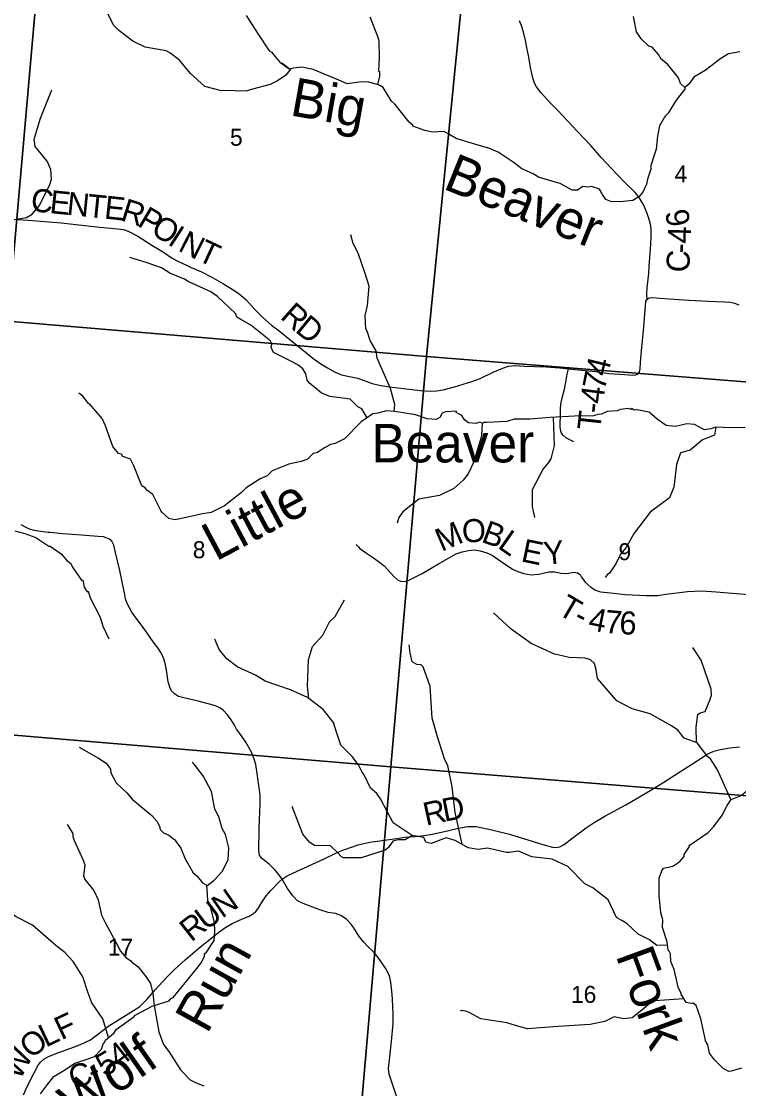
# Model space of a CAD drawing. Extents: x 1878108 to 2183446, y 146837 to 508383.
# Drawn here: x 1986826 to 1996150, y 297184 to 311060 of the extents above; entities that cross this region are included whole.
import ezdxf

# ---------------------------------------------------------------- set-up
doc = ezdxf.new("R2010")
doc.units = 0
for name, color, linetype in [('GM_X_County_Road', 7, 'Continuous'), ('GM_X_County_Road_Text', 7, 'Continuous'), ('GM_X_Minor_River', 7, 'Continuous'), ('GM_X_Minor_River_Text', 7, 'Continuous'), ('GM_X_Section', 7, 'Continuous'), ('GM_X_Section_Text', 7, 'Continuous'), ('GM_X_Township_Road', 7, 'Continuous'), ('GM_X_Township_Road_Text', 7, 'Continuous'), ('GM_X_Township_ROW', 7, 'Continuous')]:
    doc.layers.add(name, color=color, linetype=linetype)

msp = doc.modelspace()

# ---------------------------------------------------------------- linework, layer by layer
at = {"layer": 'GM_X_County_Road'}
for points in [[(1994960, 307449), (1994957, 307507), (1994963, 307594), (1994981, 307783), (1994989, 307875), (1995001, 308047), (1995007, 308171), (1995011, 308248), (1995014, 308347), (1995008, 308402), (1994987, 308485), (1994960, 308560), (1994920, 308657), (1994896, 308706), (1994855, 308771), (1994803, 308835), (1994676, 308961), (1994568, 309071), (1994364, 309291), (1994230, 309445), (1994052, 309634), (1993799, 309900), (1993706, 309996), (1993580, 310133), (1993523, 310210), (1993498, 310257), (1993478, 310310), (1993464, 310365), (1993446, 310458), (1993421, 310593), (1993406, 310677), (1993380, 310809), (1993358, 310903), (1993331, 310991), (1993301, 311066)], [(1986713, 308487), (1986919, 308474), (1987126, 308459), (1987343, 308440), (1987650, 308407), (1987845, 308386), (1988075, 308362), (1988153, 308354), (1988216, 308333), (1988338, 308266), (1988524, 308150), (1988674, 308058), (1988787, 307982), (1988860, 307942), (1988971, 307888), (1989033, 307861), (1989169, 307802), (1989301, 307733), (1989453, 307648), (1989613, 307548), (1989679, 307500), (1989742, 307444), (1989791, 307391), (1989856, 307317), (1989966, 307209), (1990078, 307110), (1990176, 307035), (1990268, 306963), (1990471, 306797), (1990616, 306682), (1990720, 306606), (1990806, 306554), (1990907, 306497), (1990989, 306466), (1991091, 306444), (1991196, 306422), (1991282, 306389), (1991387, 306351), (1991500, 306325), (1991647, 306304), (1991793, 306285), (1992010, 306260), (1992143, 306251), (1992224, 306257), (1992307, 306270), (1992458, 306308), (1992571, 306343), (1992683, 306376), (1992792, 306418), (1992958, 306497), (1993085, 306551), (1993159, 306576), (1993240, 306584), (1993362, 306577), (1993501, 306572), (1993648, 306568), (1993827, 306556), (1993937, 306544), (1994153, 306519), (1994291, 306509), (1994461, 306482), (1994669, 306467), (1994766, 306462), (1994813, 306465), (1994840, 306475), (1994861, 306502), (1994872, 306542), (1994875, 306625), (1994891, 306825), (1994912, 307037), (1994938, 307358), (1994943, 307421), (1994960, 307449)], [(1994960, 307449), (1994986, 307464), (1995029, 307470), (1995125, 307463), (1995504, 307435), (1995758, 307422), (1995971, 307415), (1996044, 307407), (1996098, 307396), (1996154, 307374)], [(1987175, 304416), (1987078, 304427), (1986998, 304442), (1986931, 304459), (1986880, 304482), (1986824, 304512)], [(1991702, 297087), (1991632, 297293), (1991605, 297372), (1991599, 297444), (1991611, 297557), (1991637, 297797), (1991660, 298031), (1991659, 298130), (1991653, 298261), (1991645, 298414), (1991628, 298569), (1991616, 298633), (1991598, 298682), (1991559, 298752), (1991495, 298845), (1991452, 298906), (1991406, 298958), (1991326, 299037), (1991281, 299086), (1991217, 299164), (1991149, 299274), (1991110, 299329), (1991051, 299388), (1990979, 299436), (1990910, 299461), (1990813, 299474), (1990707, 299508), (1990487, 299590), (1990416, 299627), (1990354, 299690), (1990285, 299786), (1990215, 299908), (1990167, 299972), (1990127, 300024), (1990096, 300056), (1990048, 300104), (1989992, 300145), (1989943, 300184), (1989922, 300219), (1989912, 300274), (1989911, 300374), (1989916, 300461), (1989918, 300575), (1989921, 300685), (1989927, 300779), (1989930, 300884), (1989928, 301005), (1989916, 301093), (1989897, 301249), (1989872, 301400), (1989853, 301468), (1989817, 301560), (1989744, 301689), (1989666, 301802), (1989624, 301858), (1989596, 301909), (1989555, 301980), (1989504, 302042), (1989452, 302100), (1989404, 302135), (1989349, 302162), (1989273, 302184), (1989125, 302222), (1988957, 302261), (1988869, 302283), (1988816, 302318), (1988779, 302356), (1988755, 302403), (1988734, 302475), (1988715, 302600), (1988699, 302696), (1988676, 302773), (1988646, 302841), (1988601, 302914), (1988538, 302994), (1988443, 303132), (1988375, 303227), (1988320, 303302), (1988264, 303379), (1988232, 303433), (1988202, 303492), (1988181, 303552), (1988166, 303628), (1988141, 303751), (1988106, 303920), (1988051, 304154), (1988030, 304250), (1988002, 304301), (1987972, 304329), (1987930, 304345), (1987892, 304357), (1987819, 304362), (1987606, 304379), (1987365, 304398), (1987196, 304414), (1987175, 304416)], [(1986852, 297102), (1986907, 297219), (1986989, 297383), (1987041, 297481), (1987071, 297525), (1987116, 297566), (1987178, 297601), (1987299, 297649), (1987470, 297710), (1987593, 297759), (1987724, 297817), (1987965, 298001), (1988146, 298112), (1988285, 298202), (1988365, 298253), (1988458, 298342), (1988571, 298471), (1988662, 298574), (1988730, 298648), (1988817, 298733), (1988956, 298860), (1989138, 299015), (1989323, 299162), (1989409, 299232), (1989485, 299284), (1989565, 299331), (1989632, 299362), (1989690, 299388), (1989786, 299428), (1989844, 299460), (1989875, 299489), (1989903, 299525), (1989947, 299601), (1990008, 299691), (1990068, 299760), (1990177, 299875), (1990215, 299908), (1990283, 299951), (1990409, 300012), (1990704, 300147), (1990968, 300270), (1991106, 300320), (1991205, 300353), (1991357, 300387), (1991514, 300409), (1991701, 300437), (1991813, 300455), (1991944, 300464), (1992064, 300474), (1992168, 300492), (1992365, 300537), (1992507, 300572), (1992628, 300592), (1992736, 300592), (1992942, 300547), (1993173, 300494), (1993605, 300357), (1993731, 300323), (1993775, 300319), (1993826, 300326), (1993881, 300357), (1993980, 300436), (1994167, 300575), (1994272, 300644), (1994410, 300725), (1994682, 300875), (1995009, 301063), (1995178, 301168), (1995374, 301293), (1995611, 301447), (1995733, 301529), (1995828, 301572), (1995913, 301594), (1996034, 301613), (1996162, 301627)]]:
    msp.add_lwpolyline(points, dxfattribs=at)
at = {"layer": 'GM_X_Minor_River'}
for points in [[(1988707, 310676), (1988437, 310726), (1988277, 310803), (1988094, 310941), (1988024, 311009), (1987945, 311171), (1987913, 311293)], [(1989747, 311136), (1989905, 310894), (1990046, 310677), (1990076, 310657), (1990187, 310531), (1990320, 310434), (1990211, 310515)], [(1991356, 311119), (1991457, 310865), (1991471, 310805), (1991476, 310589), (1991468, 310415), (1991480, 310407), (1991482, 310345), (1991456, 310238)], [(1995452, 310198), (1995395, 310252), (1995367, 310326), (1995281, 310432), (1995227, 310502), (1995142, 310570), (1995110, 310628), (1995026, 310722), (1994984, 310738), (1994883, 310832), (1994821, 310923), (1994785, 311123)], [(1996165, 310664), (1996017, 310636), (1995917, 310575), (1995713, 310419), (1995569, 310333), (1995504, 310243), (1995452, 310198), (1995450, 310176), (1995340, 310034), (1995234, 309864), (1995199, 309832), (1995187, 309814), (1995123, 309702), (1995095, 309568), (1995076, 309396), (1995042, 309294), (1995004, 309170), (1995014, 309150), (1994965, 309009), (1994953, 308941), (1994905, 308841), (1994853, 308777), (1994775, 308731), (1994611, 308713), (1994489, 308719), (1994423, 308744), (1994379, 308810), (1994371, 308824), (1994342, 308876), (1994236, 308912), (1994184, 308906), (1994126, 308912), (1994056, 308866), (1993986, 308864), (1993828, 308953), (1993764, 308969), (1993549, 309033), (1993477, 309077), (1993331, 309144), (1993219, 309230), (1993022, 309358), (1992890, 309416), (1992880, 309416), (1992605, 309497), (1992477, 309537), (1992383, 309595), (1992321, 309627), (1992171, 309620), (1992069, 309640), (1991916, 309698), (1991914, 309710), (1991868, 309748), (1991687, 309980), (1991637, 310024), (1991527, 310201), (1991485, 310225), (1991467, 310233), (1991324, 310273), (1991218, 310267), (1991062, 310247), (1990952, 310296), (1990619, 310434), (1990471, 310465), (1990361, 310453), (1990327, 310443), (1990265, 310361), (1990155, 310285), (1990059, 310237), (1989831, 310176), (1989745, 310154), (1989449, 310160), (1989429, 310157), (1989211, 310211), (1989024, 310381), (1988880, 310554), (1988757, 310652), (1988707, 310676)], [(1991486, 310335), (1991486, 310335)], [(1986736, 308484), (1986894, 308511), (1986967, 308552), (1987059, 308663), (1987180, 308900), (1987197, 308939), (1987217, 309008), (1987210, 309135), (1987163, 309241), (1987007, 309431), (1986992, 309528), (1987073, 309800), (1987220, 310168)], [(1991674, 305990), (1991680, 306077), (1991626, 306287), (1991452, 306679), (1991440, 306777), (1991358, 306909), (1991321, 307031), (1991303, 307064), (1991293, 307237), (1991326, 307365), (1991346, 307619), (1991289, 307793), (1991206, 308048), (1991140, 308172), (1991110, 308286)], [(1991321, 305906), (1991250, 306022), (1991198, 306050), (1991102, 306146), (1990837, 306184), (1990721, 306229), (1990573, 306357), (1990540, 306395), (1990522, 306477), (1990484, 306541), (1990420, 306595), (1990310, 306649), (1990105, 306756), (1990071, 306820), (1990083, 306866), (1990065, 306902), (1990047, 306918), (1989810, 307112), (1989680, 307182), (1989625, 307215), (1989611, 307263), (1989377, 307481), (1989288, 307545), (1988996, 307676), (1988946, 307710), (1988755, 307784), (1988647, 307854), (1988463, 307919), (1988235, 307988)], [(1990907, 305570), (1990843, 305559), (1990767, 305513), (1990677, 305453), (1990617, 305441), (1990547, 305369), (1990463, 305337), (1990441, 305333), (1990301, 305302), (1990087, 305218), (1990022, 305150), (1989930, 305112), (1989748, 304997), (1989688, 304933), (1989466, 304761), (1989294, 304674), (1989180, 304656), (1988892, 304590), (1988820, 304578), (1988742, 304595), (1988652, 304679), (1988640, 304701), (1988535, 304909), (1988455, 304965), (1988437, 304995), (1988391, 305023), (1988288, 305281), (1988246, 305367), (1988143, 305404), (1988129, 305432), (1988089, 305442), (1988015, 305534), (1987918, 305802), (1987878, 305898), (1987711, 306088), (1987699, 306092), (1987627, 306188), (1987571, 306227)], [(1996235, 305779), (1996040, 305775), (1995854, 305785), (1995790, 305762), (1995706, 305748), (1995576, 305820), (1995478, 305828), (1995328, 305794), (1995208, 305807), (1995093, 305889), (1994985, 305979), (1994827, 306007), (1994817, 306009), (1994793, 306005), (1994757, 306027), (1994749, 306015), (1994717, 306027), (1994615, 306012), (1994569, 305994), (1994439, 305986), (1994369, 305952), (1994319, 305950), (1994263, 305932), (1994016, 305927), (1993700, 305909), (1993436, 305888), (1993234, 305886), (1993148, 305860), (1993136, 305858), (1992876, 305843), (1992834, 305845), (1992830, 305833), (1992782, 305847), (1992736, 305831), (1992640, 305841), (1992587, 305881), (1992551, 305937), (1992477, 305976), (1992481, 305991), (1992339, 305984), (1992295, 305964), (1992271, 305920), (1992267, 305910), (1992219, 305884), (1992101, 305894), (1991949, 305942), (1991682, 305989), (1991572, 305997), (1991460, 305965), (1991394, 305955), (1991241, 305852), (1991025, 305630), (1990907, 305570)], [(1992817, 305837), (1992809, 305675), (1992798, 305639), (1992707, 305334), (1992636, 305176), (1992570, 305096), (1992448, 304988), (1992261, 304894), (1991993, 304846), (1991783, 304683), (1991731, 304608), (1991712, 304535)], [(1993741, 305911), (1993752, 305544), (1993708, 305370), (1993672, 305322), (1993611, 305240), (1993465, 304969), (1993465, 304751), (1993495, 304608)], [(1995853, 305784), (1995836, 305680), (1995679, 305618), (1995518, 305484), (1995395, 305448), (1995342, 305299), (1995306, 305004), (1995252, 304863), (1995000, 304679), (1994791, 304406), (1994685, 304216), (1994615, 304132), (1994559, 304015), (1994472, 303884), (1994442, 303862), (1994414, 303828)], [(1986741, 304438), (1986871, 304400), (1987016, 304348), (1987184, 304236), (1987200, 304235), (1987342, 304139), (1987415, 304051), (1987469, 304013), (1987489, 303963), (1987607, 303795), (1987624, 303793), (1987642, 303703), (1987682, 303643), (1987694, 303651), (1987720, 303567), (1987849, 303312), (1987887, 303198), (1987962, 303034)], [(1990564, 302258), (1990545, 302418), (1990558, 302757), (1990612, 302931), (1990745, 303080), (1990831, 303252), (1990904, 303323), (1991028, 303540)], [(1996050, 300942), (1995991, 301068), (1995876, 301327), (1995783, 301470), (1995749, 301499), (1995611, 301679), (1995440, 301739), (1995359, 301843), (1995277, 301903), (1994998, 302059), (1994765, 302121), (1994568, 302227), (1994314, 302517), (1994298, 302631), (1994275, 302713), (1994224, 302757), (1994155, 302780), (1993949, 302788), (1993801, 302826), (1993755, 302833), (1993453, 302970), (1993191, 303157), (1992962, 303368)], [(1995227, 299051), (1995087, 299044), (1994990, 299119), (1994846, 299191), (1994701, 299328), (1994631, 299369), (1994562, 299408), (1994453, 299640), (1994255, 299797), (1994152, 299848), (1993928, 300074), (1993724, 300167), (1993463, 300198), (1993289, 300273), (1993167, 300253), (1993133, 300255), (1992886, 300312), (1992762, 300292), (1992635, 300313), (1992463, 300409), (1992347, 300445), (1992153, 300372), (1992085, 300387), (1992056, 300449), (1991905, 300476), (1991661, 300639), (1991493, 300950), (1991446, 301020), (1991366, 301089), (1991284, 301262), (1991256, 301300), (1991210, 301392), (1991127, 301504), (1990979, 301649), (1990924, 301817), (1990882, 301945), (1990747, 302115), (1990545, 302270), (1990323, 302369), (1989997, 302482), (1989870, 302559), (1989630, 302670), (1989499, 302773), (1989399, 302895), (1989343, 303029)], [(1992554, 300363), (1992464, 300775), (1992426, 301106), (1992369, 301385), (1992330, 301460), (1992237, 301758), (1992166, 302002), (1992138, 302414), (1992048, 302666), (1992022, 302694), (1991966, 302700), (1991906, 302734), (1991878, 302848), (1991869, 302952)], [(1995603, 301682), (1995599, 301883), (1995618, 302049), (1995652, 302072), (1995715, 302086), (1995775, 302233), (1995798, 302300), (1995793, 302378), (1995662, 302755), (1995553, 302920)], [(1987578, 301623), (1987830, 301481), (1987928, 301414), (1987983, 301336), (1987987, 301290), (1988057, 301160), (1988196, 301032), (1988266, 300946), (1988400, 300834), (1988523, 300737), (1988589, 300663), (1988621, 300595), (1988631, 300553), (1988675, 300509), (1988744, 300479), (1988806, 300429), (1988818, 300425), (1988898, 300309), (1988957, 300173), (1989059, 299992), (1989105, 299950), (1989180, 299860), (1989240, 299824)], [(1987076, 297118), (1987167, 297238), (1987247, 297342), (1987399, 297435), (1987519, 297515), (1987693, 297573), (1987775, 297601), (1987869, 297699), (1987894, 297775), (1987906, 297785), (1987918, 297814), (1988034, 297910), (1988060, 297954), (1988294, 298122), (1988304, 298140), (1988526, 298255), (1988746, 298325), (1988767, 298357), (1988801, 298371), (1988957, 298561), (1989107, 298744), (1989164, 298820), (1989206, 298902), (1989206, 298938), (1989234, 298960), (1989242, 298972), (1989332, 299110), (1989343, 299226), (1989335, 299344), (1989289, 299530), (1989252, 299632), (1989242, 299784), (1989238, 299822), (1989334, 299896), (1989437, 300008), (1989513, 300157), (1989525, 300313), (1989480, 300488), (1989438, 300568), (1989426, 300596), (1989395, 300720), (1989343, 300818), (1989296, 301048), (1989194, 301242), (1989121, 301344), (1989049, 301428)], [(1996000, 300865), (1996051, 300943), (1996181, 300997), (1996402, 301179), (1996485, 301245), (1996685, 301266), (1996779, 301193), (1996820, 301126), (1996939, 301066), (1997081, 301036), (1997422, 300852), (1997484, 300843), (1997576, 300872)], [(1991909, 300475), (1991815, 300421), (1991726, 300421), (1991655, 300402), (1991599, 300319), (1991554, 300286), (1991435, 300244), (1991244, 300185), (1991015, 300184), (1990986, 300196), (1990934, 300256), (1990845, 300343), (1990636, 300345), (1990577, 300385), (1990506, 300466), (1990486, 300494), (1990348, 300851)], [(1996186, 297449), (1996054, 297412), (1996022, 297408), (1995951, 297446), (1995835, 297560), (1995773, 297646), (1995748, 297754), (1995720, 297804), (1995718, 297816), (1995659, 298092), (1995597, 298266), (1995559, 298297), (1995531, 298293), (1995467, 298305), (1995402, 298411), (1995404, 298423), (1995366, 298503), (1995338, 298621), (1995313, 298731), (1995267, 298839), (1995265, 298937), (1995245, 298971), (1995235, 298985), (1995222, 299093), (1995160, 299281), (1995166, 299379), (1995137, 299469), (1995115, 299695), (1995118, 299919), (1995152, 300017), (1995174, 300049), (1995296, 300077), (1995386, 300139), (1995441, 300203), (1995443, 300229), (1995513, 300333), (1995507, 300345), (1995519, 300355), (1995753, 300516), (1995825, 300586), (1995930, 300730), (1996000, 300865)], [(1987422, 300617), (1987497, 300501), (1987493, 300459), (1987517, 300401), (1987630, 300153), (1987650, 300095), (1987634, 299951), (1987650, 299905), (1987767, 299761), (1987825, 299639), (1987868, 299439), (1987914, 299346), (1988061, 299072), (1988115, 298970), (1988188, 298886), (1988246, 298848), (1988256, 298834), (1988342, 298770), (1988446, 298644), (1988503, 298553), (1988537, 298421), (1988552, 298263)], [(1987960, 297848), (1987883, 298091), (1987742, 298298), (1987688, 298440), (1987625, 298639), (1987500, 298839), (1987392, 298955), (1987273, 299047), (1986972, 299309), (1986758, 299418), (1986690, 299471), (1986511, 299675), (1986248, 299831), (1986148, 299945), (1986111, 300116), (1986098, 300308), (1986096, 300340)], [(1995438, 298352), (1995062, 298326), (1995025, 298316), (1994893, 298205), (1994766, 298103), (1994652, 298090), (1994532, 298117), (1994409, 298055), (1994221, 298017), (1993804, 297993), (1993406, 297962), (1993250, 298005), (1993136, 298041), (1992800, 298092), (1992647, 298173), (1992602, 298192), (1992543, 298200), (1992533, 298190)], [(1988553, 298264), (1988613, 297923), (1988673, 297757), (1988745, 297669), (1988896, 297429), (1989021, 297298), (1989097, 297258), (1989198, 297222)]]:
    msp.add_lwpolyline(points, dxfattribs=at)
at = {"layer": 'GM_X_Section'}
for points in [[(1987122, 312538), (1986650, 307162), (1981193, 307678), (1981689, 313028)], [(1987478, 312502), (1992620, 312034), (1992094, 306704), (1986650, 307162), (1987122, 312538)], [(1992928, 312010), (1998077, 311612), (1997595, 306264), (1992094, 306704), (1992620, 312034)], [(1992094, 306704), (1991629, 301367), (1986164, 301829), (1986650, 307162)], [(1997595, 306264), (1997113, 300923), (1991629, 301367), (1992094, 306704)], [(1986164, 301829), (1991629, 301367), (1991165, 296023), (1985670, 296467)], [(1997113, 300923), (1996673, 295553), (1991165, 296023), (1991629, 301367)]]:
    msp.add_lwpolyline(points, close=True, dxfattribs=at)
at = {"layer": 'GM_X_Township_Road'}
for points in [[(1994008, 305595), (1993965, 305613), (1993913, 305642), (1993872, 305674), (1993846, 305705), (1993837, 305731), (1993829, 305782), (1993831, 305832), (1993836, 305930), (1993835, 306018), (1993837, 306081), (1993855, 306167), (1993885, 306279), (1993905, 306368), (1993920, 306472), (1993937, 306544)], [(1991213, 304222), (1991223, 304210), (1991299, 304156), (1991402, 304086), (1991484, 304025), (1991543, 303979), (1991594, 303926), (1991668, 303842), (1991717, 303800), (1991758, 303782), (1991808, 303777), (1991854, 303791), (1992036, 303880), (1992247, 304007), (1992478, 304135), (1992554, 304161), (1992639, 304181), (1992711, 304190), (1992789, 304178), (1992876, 304152), (1992947, 304121), (1993050, 304045), (1993209, 303939), (1993280, 303907), (1993356, 303883), (1993451, 303866), (1993551, 303872), (1993681, 303901), (1993758, 303901), (1993845, 303887), (1993915, 303883), (1993986, 303896)], [(1993986, 303896), (1994005, 303900), (1994056, 303892), (1994091, 303867), (1994109, 303835), (1994154, 303768), (1994227, 303704), (1994291, 303664), (1994354, 303641), (1994526, 303626), (1994676, 303609), (1994948, 303597), (1995096, 303597), (1995202, 303611), (1995484, 303649), (1995672, 303657), (1995857, 303644), (1996329, 303603)]]:
    msp.add_lwpolyline(points, dxfattribs=at)
at = {"layer": 'GM_X_Township_ROW'}
msp.add_lwpolyline([(1991180, 304259), (1991213, 304222)], dxfattribs=at)

# ---------------------------------------------------------------- texts
at = {"layer": 'GM_X_County_Road_Text'}
for s, rotation, p in [('C', 354.2374, (1986940, 308593)), ('E', 354.2348, (1987185, 308568)), ('N', 354.2382, (1987408, 308546)), ('T', 354.2303, (1987671, 308519)), ('E', 353.8986, (1987894, 308497)), ('R', 342.4932, (1988102, 308476)), ('P', 329.1206, (1988320, 308410)), ('6', 100.6895, (1995527, 308422)), ('O', 328.6708, (1988493, 308306)), ('I', 326.875, (1988716, 308170)), ('N', 333.1151, (1988850, 308085)), ('4', 88.7124, (1995528, 308169)), ('T', 335.1134, (1989096, 307961)), ('C', 86.487, (1995505, 307788)), ('-', 86.7065, (1995521, 308035)), ('R', 318.1671, (1990178, 307206)), ('D', 320.7641, (1990372, 307032)), ('D', 11.0181, (1992325, 300653)), ('R', 12.4945, (1992086, 300600)), ('N', 34.7307, (1989435, 299391)), ('U', 36.7001, (1989226, 299234)), ('R', 38.302, (1989034, 299083)), ('F', 25.2198, (1987346, 297812)), ('O', 37.9464, (1986950, 297563)), ('L', 25.3968, (1987143, 297716)), ('4', 38.0542, (1988100, 297448)), ('W', 61.5774, (1986805, 297282)), ('5', 30.7039, (1987907, 297330)), ('C', 19.6143, (1987504, 297171)), ('-', 23.6887, (1987758, 297262))]:
    msp.add_text(s, height=300, rotation=rotation, dxfattribs=at).set_placement(p)
at = {"layer": 'GM_X_Minor_River_Text'}
for s, rotation, p in [('Big', 349.9997, (1990305, 309840)), ('Beaver', 337.9972, (1992292, 308889)), ('Beaver', 359.9996, (1991375, 305326)), ('Little', 28.0034, (1989354, 304034)), ('Run', 61.0006, (1989241, 297884)), ('Fork', 290.106, (1994548, 298918)), ('Wolf', 35.0008, (1987543, 296734))]:
    msp.add_text(s, height=500, rotation=rotation, dxfattribs=at).set_placement(p)
at = {"layer": 'GM_X_Section_Text'}
for s, p in [('5', (1989538, 309442)), ('4', (1995317, 308966)), ('8', (1989054, 304080)), ('9', (1994589, 304054)), ('17', (1987950, 298913)), ('16', (1993971, 298299))]:
    msp.add_text(s, height=221, rotation=0, dxfattribs=at).set_placement(p)
at = {"layer": 'GM_X_Township_Road_Text'}
for s, rotation, p in [('4', 76.5014, (1994446, 306432)), ('7', 78.3915, (1994410, 306253)), ('4', 82.7678, (1994387, 306076)), ('T', 83.8706, (1994350, 305732)), ('-', 83.7154, (1994374, 305955)), ('O', 1.7707, (1992557, 304284)), ('M', 23.4443, (1992288, 304161)), ('B', 339.9745, (1992792, 304297)), ('L', 325.0903, (1993005, 304222)), ('E', 348.3123, (1993310, 304041)), ('Y', 5.895, (1993630, 303991)), ('T', 329.6518, (1993780, 303363)), ('-', 331.8323, (1993984, 303243)), ('4', 348.5663, (1994182, 303153)), ('7', 355.2081, (1994401, 303111)), ('6', 356.6606, (1994593, 303095))]:
    msp.add_text(s, height=300, rotation=rotation, dxfattribs=at).set_placement(p)

doc.saveas('drawing.dxf')
